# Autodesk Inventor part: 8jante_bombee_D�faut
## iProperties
Created: 2011-01
Part Number: 8jante_bombee_D�faut
Document SubType Name: Modeling
Designer: eric
Density: 1 g/cm^3
Mass: 137.725 g
Surface Area: 1288.94 cm^2
Volume: 137.725 cm^3
Author: eric
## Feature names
1. Base1
